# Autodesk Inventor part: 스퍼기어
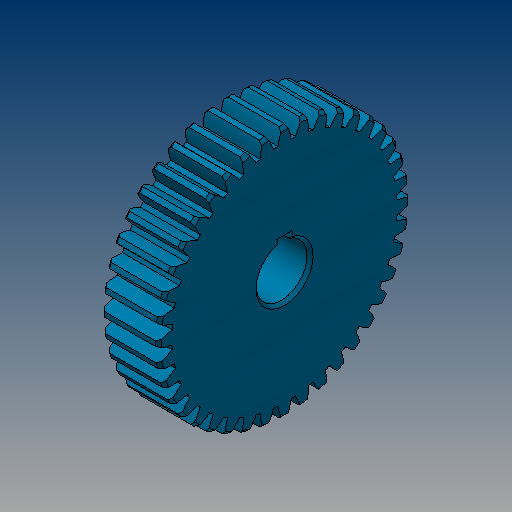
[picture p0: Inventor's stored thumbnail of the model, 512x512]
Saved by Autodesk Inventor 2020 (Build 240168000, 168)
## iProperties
CustomPartVersion: 1
Created: 2018-11
Part Number: 스퍼기어
Material: 알루미늄 6061
Document SubType Name: Modeling
Designer: mduedu
Categories: <?xml version="1.0" encoding="UTF-16"?> <MemberInstance><Categories><FamilyTemplate><FamilyTemplateParameter ValueType="xs:double" Id="1" ObjectReferenceKey="da
Density: 1 g/cm^3
Appearance: 하늘색 중간
Author: mduedu
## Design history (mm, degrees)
sketch "Sketch1"
  geometry: C1 r 42 at (0, 0)
  constraints: 1 centre point
  dimensions: "d0" = 83.99905 diameter of C1 (= da_da)
extrude "Extrusion1" new body sketch "Sketch1" distance "d1" = 19 (= da_b); taper "d2" = 0 deg
workplane "Work Plane2"
sketch "Sketch2"
  geometry: C1 r 42 at (0, 0) reference; C2 r 40.05 at (0, 0)
  constraints: 1 centre point, 1 coincident
  dimensions: "d3" = 80.10038 diameter of C2 (= da_dw)
feature "피치 지름" sketch "Sketch2" dims "d4" = 10, "d5" = 0
workplane "Work Plane8"
workplane "Work Plane9"
feature "스퍼 기어" dims "d17" = 0, "d54" = 17, "d56" = 19.3, "d57" = 5, "da_b" = 19, "da_d" = 80, "da_aw" = 80.10038, "da_da" = 83.99905, "da_df" = 75, "da_dw" = 80.10038, angle "da_beta" = 0 deg, "da_lefttooth" = 0, "da_righttooth" = 0
sketch "스케치3"
  geometry: L1 (-42, 19)-(42, 19) reference; L2 (42, 19)-(42, 0) reference; L3 (42, 0)-(-42, 0) reference; L4 (-42, 0)-(-42, 19) reference; L5 (0, 0)-(0, 19); L6 (42, 0)-(41, 0); L7 (42, 1)-(42, 0); L8 (42, 19)-(41, 19); L9 (42, 18)-(42, 19); L10 (41, 19)-(42, 18); L11 (41, 0)-(42, 1)
  constraints: 14 end point, 2 horizontal, 2 vertical, 1 midpoint
  dimensions: "d49" = 1 distance from line of L8.end L2; "d50" = 1 horizontal distance of L8.end L9.start; "d51" = 1 horizontal distance of L6.end L7.start; "d52" = 1 horizontal distance of L6.end L7.start
revolve "회전1" sketch "스케치3" stored, may be unused: angle "d53" = 90 deg
sketch "스케치4"
  geometry: L1 (-2.5, 8.124)-(2.5, 8.124); L2 (2.5, 8.124)-(2.5, 10.8); L3 (2.5, 10.8)-(-2.5, 10.8); L4 (-2.5, 10.8)-(-2.5, 8.124); A1 r 8.5 centre (0, 0) between (-2.5, 8.124) and (2.5, 8.124); 1 further point
  constraints: 8 end point, 2 parallel, 2 point on circle, 1 centre point, 1 coincident, 1 horizontal, 1 perpendicular
  dimensions: "d54" = 17 diameter of A1; "d56" = 19.3 dimension on A1 L3; "d57" = 5 distance of L2.end L3.end
extrude "돌출2" cut sketch "스케치4" extent not by distance; stored distance "d58" = 10; taper "d59" = 0 deg
chamfer "모따기1" distance "d60" = 1; stored, may be unused: second distance "d61" = 2, angle "d62" = 45 deg
sketch "스케치5"
  geometry: C1 r 17.5 at (0, 0); C2 r 28.5 at (0, 0); 1 further point
  constraints: 2 centre point, 2 coincident
  dimensions: "d63" = 35 diameter of C1; "d64" = 57 diameter of C2
extrude "돌출3" cut sketch "스케치5" distance "d65" = 9.5; taper "d66" = 0 deg
fillet "모깎기1" dims "d67" = 3
body "Solid1"
body "Srf1"
node "절단 모서리 투영1"
other parameters: "d16" = 80.10038 (= da_aw), "d34" = 4.5 deg (computed from da_z), "d39" = 0, "d41" = 0, "d43" = 80.10038 (= da_aw), "d46" = 80.10038 (= da_aw), "d47" = 0, "d48" = 0
